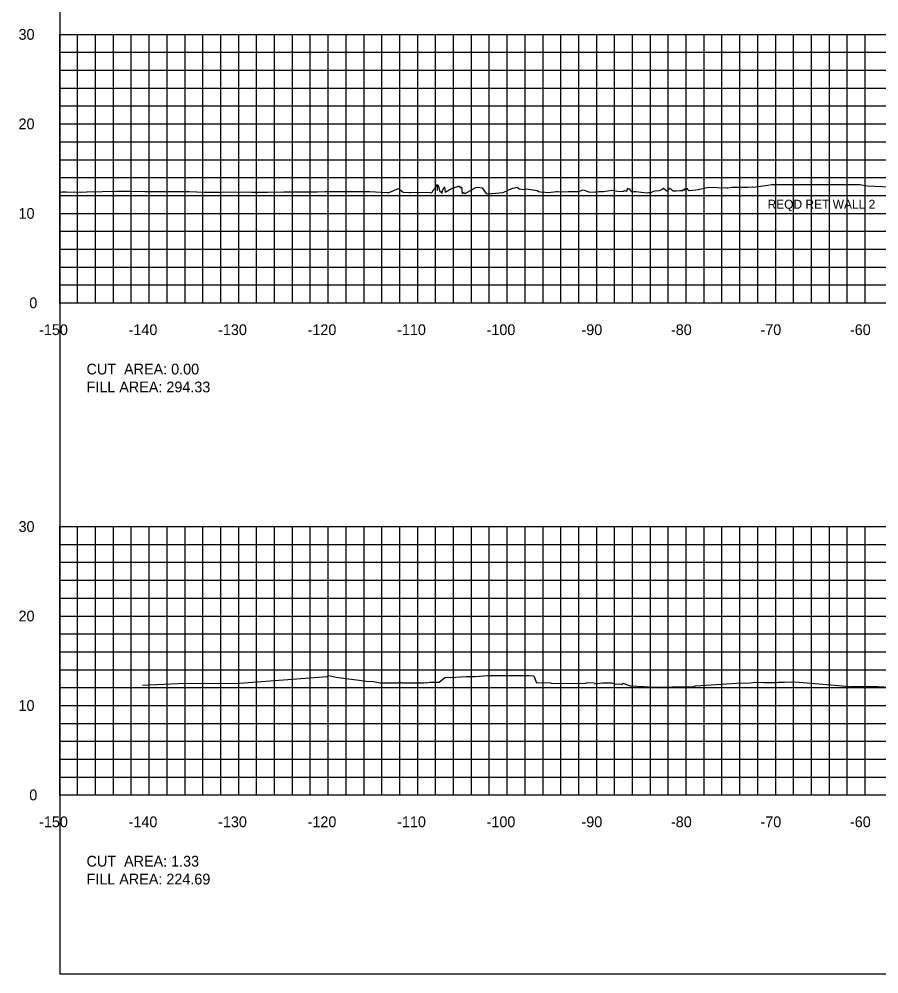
# Model space of a CAD drawing. Extents: x 1797518 to 1804843, y 248068 to 251132.
# Drawn here: x 1802136.5 to 1802232.5, y 250079.4 to 250186.1 of the extents above; entities that cross this region are included whole.
import ezdxf

# ---------------------------------------------------------------- set-up
doc = ezdxf.new("R2010")
doc.units = 0
for name, color, linetype in [('10', 7, 'Continuous'), ('3', 7, 'Continuous'), ('31', 7, 'Continuous'), ('60', 7, 'Continuous'), ('ANNO-TXT', 7, 'Continuous'), ('Level 62', 7, 'Continuous'), ('M-ROADS', 7, 'Continuous')]:
    doc.layers.add(name, color=color, linetype=linetype)

msp = doc.modelspace()

# ---------------------------------------------------------------- linework, layer by layer
msp.add_lwpolyline([(1802141, 250079.43), (1802441, 250079.43), (1802441, 250269.43), (1802141, 250269.43)], close=True)
at = {"layer": '60'}
for p, q in [((1802140.94, 250184.43), (1802141, 250184.43)), ((1802141, 250154.43), (1802141, 250184.43)), ((1802140.94, 250174.43), (1802141, 250174.43)), ((1802140.94, 250164.43), (1802141, 250164.43)), ((1802140.94, 250154.43), (1802141, 250154.43)), ((1802141, 250154.43), (1802441, 250154.43)), ((1802141, 250154.37), (1802141, 250154.43)), ((1802151, 250154.37), (1802151, 250154.43)), ((1802161, 250154.37), (1802161, 250154.43)), ((1802171, 250154.37), (1802171, 250154.43)), ((1802181, 250154.37), (1802181, 250154.43)), ((1802191, 250154.37), (1802191, 250154.43)), ((1802201, 250154.37), (1802201, 250154.43)), ((1802211, 250154.37), (1802211, 250154.43)), ((1802221, 250154.37), (1802221, 250154.43)), ((1802231, 250154.37), (1802231, 250154.43)), ((1802140.94, 250129.43), (1802141, 250129.43)), ((1802141, 250099.43), (1802141, 250129.43)), ((1802140.94, 250119.43), (1802141, 250119.43)), ((1802140.94, 250109.43), (1802141, 250109.43)), ((1802140.94, 250099.43), (1802141, 250099.43)), ((1802141, 250099.43), (1802441, 250099.43)), ((1802141, 250099.37), (1802141, 250099.43)), ((1802151, 250099.37), (1802151, 250099.43)), ((1802161, 250099.37), (1802161, 250099.43)), ((1802171, 250099.37), (1802171, 250099.43)), ((1802181, 250099.37), (1802181, 250099.43)), ((1802191, 250099.37), (1802191, 250099.43)), ((1802201, 250099.37), (1802201, 250099.43)), ((1802211, 250099.37), (1802211, 250099.43)), ((1802221, 250099.37), (1802221, 250099.43)), ((1802231, 250099.37), (1802231, 250099.43))]:
    msp.add_line(p, q, dxfattribs=at)
at = {"layer": 'Level 62'}
for p, q in [((1802141, 250184.43), (1802441, 250184.43)), ((1802141, 250154.43), (1802141, 250184.43)), ((1802143, 250154.43), (1802143, 250184.43)), ((1802145, 250154.43), (1802145, 250184.43)), ((1802147, 250154.43), (1802147, 250184.43)), ((1802149, 250154.43), (1802149, 250184.43)), ((1802151, 250154.43), (1802151, 250184.43)), ((1802153, 250154.43), (1802153, 250184.43)), ((1802155, 250154.43), (1802155, 250184.43)), ((1802157, 250154.43), (1802157, 250184.43)), ((1802159, 250154.43), (1802159, 250184.43)), ((1802161, 250154.43), (1802161, 250184.43)), ((1802163, 250154.43), (1802163, 250184.43)), ((1802165, 250154.43), (1802165, 250184.43)), ((1802167, 250154.43), (1802167, 250184.43)), ((1802169, 250154.43), (1802169, 250184.43)), ((1802171, 250154.43), (1802171, 250184.43)), ((1802173, 250154.43), (1802173, 250184.43)), ((1802175, 250154.43), (1802175, 250184.43)), ((1802177, 250154.43), (1802177, 250184.43)), ((1802179, 250154.43), (1802179, 250184.43)), ((1802181, 250154.43), (1802181, 250184.43)), ((1802183, 250154.43), (1802183, 250184.43)), ((1802185, 250154.43), (1802185, 250184.43)), ((1802187, 250154.43), (1802187, 250184.43)), ((1802189, 250154.43), (1802189, 250184.43)), ((1802191, 250154.43), (1802191, 250184.43)), ((1802193, 250154.43), (1802193, 250184.43)), ((1802195, 250154.43), (1802195, 250184.43)), ((1802197, 250154.43), (1802197, 250184.43)), ((1802199, 250154.43), (1802199, 250184.43)), ((1802201, 250154.43), (1802201, 250184.43)), ((1802203, 250154.43), (1802203, 250184.43)), ((1802205, 250154.43), (1802205, 250184.43)), ((1802207, 250154.43), (1802207, 250184.43)), ((1802209, 250154.43), (1802209, 250184.43)), ((1802211, 250154.43), (1802211, 250184.43)), ((1802213, 250154.43), (1802213, 250184.43)), ((1802215, 250154.43), (1802215, 250184.43)), ((1802217, 250154.43), (1802217, 250184.43)), ((1802219, 250154.43), (1802219, 250184.43)), ((1802221, 250154.43), (1802221, 250184.43)), ((1802223, 250154.43), (1802223, 250184.43)), ((1802225, 250154.43), (1802225, 250184.43)), ((1802227, 250154.43), (1802227, 250184.43)), ((1802229, 250154.43), (1802229, 250184.43)), ((1802231, 250154.43), (1802231, 250184.43)), ((1802141, 250182.43), (1802441, 250182.43)), ((1802141, 250180.43), (1802441, 250180.43)), ((1802141, 250178.43), (1802441, 250178.43)), ((1802141, 250176.43), (1802441, 250176.43)), ((1802141, 250174.43), (1802441, 250174.43)), ((1802141, 250172.43), (1802441, 250172.43)), ((1802141, 250170.43), (1802441, 250170.43)), ((1802141, 250168.43), (1802441, 250168.43)), ((1802141, 250166.43), (1802441, 250166.43)), ((1802141, 250164.43), (1802441, 250164.43)), ((1802141, 250162.43), (1802441, 250162.43)), ((1802141, 250160.43), (1802441, 250160.43)), ((1802141, 250158.43), (1802441, 250158.43)), ((1802141, 250156.43), (1802441, 250156.43)), ((1802141, 250154.43), (1802441, 250154.43)), ((1802141, 250129.43), (1802441, 250129.43)), ((1802141, 250099.43), (1802141, 250129.43)), ((1802143, 250099.43), (1802143, 250129.43)), ((1802145, 250099.43), (1802145, 250129.43)), ((1802147, 250099.43), (1802147, 250129.43)), ((1802149, 250099.43), (1802149, 250129.43)), ((1802151, 250099.43), (1802151, 250129.43)), ((1802153, 250099.43), (1802153, 250129.43)), ((1802155, 250099.43), (1802155, 250129.43)), ((1802157, 250099.43), (1802157, 250129.43)), ((1802159, 250099.43), (1802159, 250129.43)), ((1802161, 250099.43), (1802161, 250129.43)), ((1802163, 250099.43), (1802163, 250129.43)), ((1802165, 250099.43), (1802165, 250129.43)), ((1802167, 250099.43), (1802167, 250129.43)), ((1802169, 250099.43), (1802169, 250129.43)), ((1802171, 250099.43), (1802171, 250129.43)), ((1802173, 250099.43), (1802173, 250129.43)), ((1802175, 250099.43), (1802175, 250129.43)), ((1802177, 250099.43), (1802177, 250129.43)), ((1802179, 250099.43), (1802179, 250129.43)), ((1802181, 250099.43), (1802181, 250129.43)), ((1802183, 250099.43), (1802183, 250129.43)), ((1802185, 250099.43), (1802185, 250129.43)), ((1802187, 250099.43), (1802187, 250129.43)), ((1802189, 250099.43), (1802189, 250129.43)), ((1802191, 250099.43), (1802191, 250129.43)), ((1802193, 250099.43), (1802193, 250129.43)), ((1802195, 250099.43), (1802195, 250129.43)), ((1802197, 250099.43), (1802197, 250129.43)), ((1802199, 250099.43), (1802199, 250129.43)), ((1802201, 250099.43), (1802201, 250129.43)), ((1802203, 250099.43), (1802203, 250129.43)), ((1802205, 250099.43), (1802205, 250129.43)), ((1802207, 250099.43), (1802207, 250129.43)), ((1802209, 250099.43), (1802209, 250129.43)), ((1802211, 250099.43), (1802211, 250129.43)), ((1802213, 250099.43), (1802213, 250129.43)), ((1802215, 250099.43), (1802215, 250129.43)), ((1802217, 250099.43), (1802217, 250129.43)), ((1802219, 250099.43), (1802219, 250129.43)), ((1802221, 250099.43), (1802221, 250129.43)), ((1802223, 250099.43), (1802223, 250129.43)), ((1802225, 250099.43), (1802225, 250129.43)), ((1802227, 250099.43), (1802227, 250129.43)), ((1802229, 250099.43), (1802229, 250129.43)), ((1802231, 250099.43), (1802231, 250129.43)), ((1802141, 250127.43), (1802441, 250127.43)), ((1802141, 250125.43), (1802441, 250125.43)), ((1802141, 250123.43), (1802441, 250123.43)), ((1802141, 250121.43), (1802441, 250121.43)), ((1802141, 250119.43), (1802441, 250119.43)), ((1802141, 250117.43), (1802441, 250117.43)), ((1802141, 250115.43), (1802441, 250115.43)), ((1802141, 250113.43), (1802441, 250113.43)), ((1802141, 250111.43), (1802441, 250111.43)), ((1802141, 250109.43), (1802441, 250109.43)), ((1802141, 250107.43), (1802441, 250107.43)), ((1802141, 250105.43), (1802441, 250105.43)), ((1802141, 250103.43), (1802441, 250103.43)), ((1802141, 250101.43), (1802441, 250101.43)), ((1802141, 250099.43), (1802441, 250099.43))]:
    msp.add_line(p, q, dxfattribs=at)
at = {"layer": 'M-ROADS'}
for points in [[(1802141, 250166.81), (1802141.26, 250166.83), (1802141.73, 250166.83), (1802143.31, 250166.81), (1802144.04, 250166.82), (1802145.79, 250166.88), (1802147.35, 250166.9), (1802148.93, 250166.9), (1802150.54, 250166.89), (1802152.16, 250166.89), (1802153.81, 250166.86), (1802155.48, 250166.86), (1802157.18, 250166.8), (1802158.9, 250166.8), (1802160.65, 250166.82), (1802162.41, 250166.81), (1802164.21, 250166.81), (1802166.04, 250166.82), (1802167.88, 250166.83), (1802167.97, 250166.83), (1802169.82, 250166.84), (1802170.61, 250166.89), (1802172.04, 250166.87), (1802173.66, 250166.88), (1802174.24, 250166.88), (1802175.52, 250166.88), (1802175.65, 250166.88), (1802177.6, 250166.75), (1802177.62, 250166.75), (1802177.66, 250166.75), (1802177.71, 250166.74), (1802178.85, 250167.22), (1802179.37, 250166.81), (1802180.04, 250166.76), (1802180.24, 250166.76), (1802181.56, 250166.8), (1802182.37, 250166.78), (1802182.53, 250166.73), (1802182.62, 250166.79), (1802182.78, 250167.06), (1802182.95, 250167.24), (1802183, 250167.42), (1802183.12, 250167.43), (1802183.14, 250167.65), (1802183.18, 250166.99), (1802183.2, 250167.03), (1802183.24, 250167.62), (1802183.26, 250167.53), (1802183.3, 250167.59), (1802183.49, 250166.88), (1802183.56, 250166.89), (1802183.69, 250166.64), (1802183.81, 250167.06), (1802183.97, 250167.33), (1802184, 250167.41), (1802184.08, 250166.79), (1802184.78, 250167.21), (1802185, 250167.3), (1802185.58, 250167.48), (1802185.65, 250167.46), (1802185.85, 250167.29), (1802185.87, 250167.35), (1802185.88, 250167.37), (1802185.97, 250166.67), (1802185.97, 250166.65), (1802186.1, 250166.76), (1802186.3, 250166.66), (1802187.5, 250167.31), (1802187.71, 250167.35), (1802188.2, 250167.27), (1802188.65, 250166.64), (1802188.75, 250166.63), (1802189.26, 250166.66), (1802190.56, 250166.78), (1802191.59, 250167.24), (1802191.89, 250167.3), (1802192.06, 250167.34), (1802192.38, 250167.18), (1802192.81, 250167.09), (1802193.17, 250167.18), (1802194.34, 250166.99), (1802194.51, 250166.86), (1802194.72, 250166.85), (1802195.26, 250166.79), (1802195.57, 250166.76), (1802196.49, 250166.86), (1802196.64, 250166.87), (1802196.94, 250166.84), (1802197.81, 250166.88), (1802198.24, 250166.88), (1802198.94, 250166.87), (1802199.07, 250166.91), (1802199.5, 250167.06), (1802200, 250166.88), (1802200.25, 250166.8), (1802200.81, 250166.85), (1802201, 250166.85), (1802201.23, 250166.87), (1802201.76, 250166.87), (1802202.7, 250167.04), (1802202.97, 250166.97), (1802203.5, 250166.88), (1802203.51, 250166.88), (1802203.99, 250166.91), (1802204.09, 250166.97), (1802204.2, 250166.95), (1802204.36, 250166.93), (1802204.37, 250166.92), (1802204.44, 250167.18), (1802204.45, 250167.18), (1802204.45, 250167.23), (1802204.57, 250167.18), (1802204.66, 250167.2), (1802204.67, 250167.21), (1802204.74, 250167.02), (1802204.92, 250166.89), (1802205.42, 250166.87), (1802205.95, 250166.8), (1802206.68, 250166.74), (1802206.82, 250166.75), (1802207.09, 250166.77), (1802207.33, 250166.9), (1802207.5, 250166.95), (1802208.02, 250166.97), (1802208.27, 250167.11), (1802208.29, 250167.11), (1802208.3, 250167.15), (1802208.48, 250167.25), (1802208.72, 250167.02), (1802208.83, 250166.96), (1802208.98, 250166.96), (1802208.99, 250166.96), (1802208.99, 250166.96), (1802209.05, 250167.11), (1802209.06, 250167.15), (1802209.06, 250167.13), (1802209.19, 250167.23), (1802209.44, 250167.02), (1802209.51, 250166.94), (1802209.89, 250166.95), (1802210.29, 250166.98), (1802210.62, 250166.98), (1802210.74, 250167.12), (1802210.82, 250166.98), (1802210.82, 250166.97), (1802210.82, 250166.99), (1802210.83, 250167.22), (1802210.88, 250167.15), (1802210.9, 250167.13), (1802210.96, 250167.13), (1802210.96, 250167.22), (1802210.96, 250167.15), (1802211.07, 250167.16), (1802211.1, 250167.23), (1802211.12, 250167.14), (1802211.16, 250167.15), (1802211.31, 250167), (1802211.31, 250166.99), (1802211.36, 250166.98), (1802211.75, 250167.02), (1802212.34, 250167.1), (1802213.51, 250167.35), (1802215.51, 250167.29), (1802215.63, 250167.29), (1802215.65, 250167.3), (1802216.12, 250167.35), (1802217.89, 250167.35), (1802218.36, 250167.39), (1802218.48, 250167.35), (1802220.12, 250167.6), (1802220.52, 250167.66), (1802220.95, 250167.66), (1802223.26, 250167.66), (1802225.42, 250167.65), (1802226.02, 250167.65), (1802227.78, 250167.65), (1802228.23, 250167.65), (1802228.41, 250167.65), (1802230.39, 250167.65), (1802231.25, 250167.52), (1802234.58, 250167.36)], [(1802150.26, 250111.72), (1802154.24, 250111.87), (1802161.1, 250111.93), (1802170.88, 250112.67), (1802171.07, 250112.79), (1802171.9, 250112.59), (1802175.56, 250112.12), (1802175.88, 250112.16), (1802176.81, 250111.97), (1802177.96, 250111.97), (1802178.83, 250111.97), (1802179.02, 250112.04), (1802179.03, 250112.02), (1802179.1, 250111.98), (1802179.16, 250111.98), (1802179.28, 250111.99), (1802179.29, 250112.01), (1802179.31, 250111.97), (1802179.44, 250111.97), (1802179.59, 250111.97), (1802179.85, 250111.97), (1802181.09, 250111.97), (1802181.72, 250111.97), (1802181.97, 250111.99), (1802182.02, 250111.98), (1802182.03, 250111.98), (1802182.34, 250112.02), (1802182.45, 250112.04), (1802183.38, 250112.04), (1802184.03, 250112.57), (1802184.29, 250112.58), (1802184.62, 250112.54), (1802186.41, 250112.66), (1802187.44, 250112.66), (1802188.81, 250112.77), (1802189.22, 250112.79), (1802191.56, 250112.79), (1802193.47, 250112.79), (1802193.97, 250112.73), (1802194.29, 250111.97), (1802194.36, 250111.99), (1802195.86, 250111.97), (1802195.88, 250111.94), (1802199.72, 250111.87), (1802199.99, 250112), (1802200.75, 250111.98), (1802200.8, 250111.85), (1802201.64, 250111.95), (1802202.65, 250111.97), (1802203.14, 250111.8), (1802203.58, 250111.85), (1802203.74, 250111.81), (1802203.8, 250111.79), (1802203.95, 250111.93), (1802204.03, 250111.9), (1802204.5, 250111.72), (1802204.74, 250111.64), (1802206.28, 250111.56), (1802206.78, 250111.5), (1802208.61, 250111.48), (1802208.95, 250111.48), (1802209.03, 250111.49), (1802209.43, 250111.51), (1802210.96, 250111.51), (1802211.74, 250111.5), (1802212.03, 250111.61), (1802216.67, 250111.93), (1802218.17, 250111.98), (1802218.66, 250112.02), (1802219.65, 250112.01), (1802220.94, 250112.01), (1802221.27, 250112.03), (1802221.42, 250112.04), (1802222, 250112.04), (1802222.82, 250112.09), (1802223.61, 250112.02), (1802228.47, 250111.61), (1802229.14, 250111.55), (1802229.27, 250111.53), (1802229.37, 250111.55), (1802231.53, 250111.54), (1802231.87, 250111.57), (1802232.07, 250111.55), (1802232.38, 250111.57), (1802233.82, 250111.47)]]:
    msp.add_lwpolyline(points, dxfattribs=at)

# ---------------------------------------------------------------- texts
at = {"layer": '10'}
for s, p in [('-150', (1802138.7, 250150.83)), ('-140', (1802148.7, 250150.83)), ('-130', (1802158.7, 250150.83)), ('-120', (1802168.7, 250150.83)), ('-110', (1802178.7, 250150.83)), ('-100', (1802188.7, 250150.83)), ('-90', (1802199.3, 250150.83)), ('-80', (1802209.3, 250150.83)), ('-70', (1802219.3, 250150.83)), ('-60', (1802229.3, 250150.83)), ('-150', (1802138.7, 250095.83)), ('-140', (1802148.7, 250095.83)), ('-130', (1802158.7, 250095.83)), ('-120', (1802168.7, 250095.83)), ('-110', (1802178.7, 250095.83)), ('-100', (1802188.7, 250095.83)), ('-90', (1802199.3, 250095.83)), ('-80', (1802209.3, 250095.83)), ('-70', (1802219.3, 250095.83)), ('-60', (1802229.3, 250095.83))]:
    msp.add_text(s, height=1.2, dxfattribs=at).set_placement(p)
at = {"layer": '3'}
msp.add_text('REQD RET WALL 2', height=1, dxfattribs=at).set_placement((1802220.09, 250164.95))
at = {"layer": '31'}
for s, p in [('30', (1802136.4, 250183.83)), ('20', (1802136.4, 250173.83)), ('10', (1802136.4, 250163.83)), ('0', (1802137.6, 250153.83)), ('30', (1802136.4, 250128.83)), ('20', (1802136.4, 250118.83)), ('10', (1802136.4, 250108.83)), ('0', (1802137.6, 250098.83))]:
    msp.add_text(s, height=1.2, dxfattribs=at).set_placement(p)
at = {"layer": '60'}
for p in [(1802141, 250154.43), (1802141, 250099.43)]:
    msp.add_text('-', height=0.0001, dxfattribs=at).set_placement(p)
at = {"layer": 'ANNO-TXT'}
for s, p in [('CUT  AREA: 0.00', (1802144, 250146.43)), ('FILL AREA: 294.33', (1802144, 250144.43)), ('CUT  AREA: 1.33', (1802144, 250091.43)), ('FILL AREA: 224.69', (1802144, 250089.43))]:
    msp.add_text(s, height=1.2, dxfattribs=at).set_placement(p)

doc.saveas('drawing.dxf')
